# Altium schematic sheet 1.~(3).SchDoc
size 420 x 297 mm
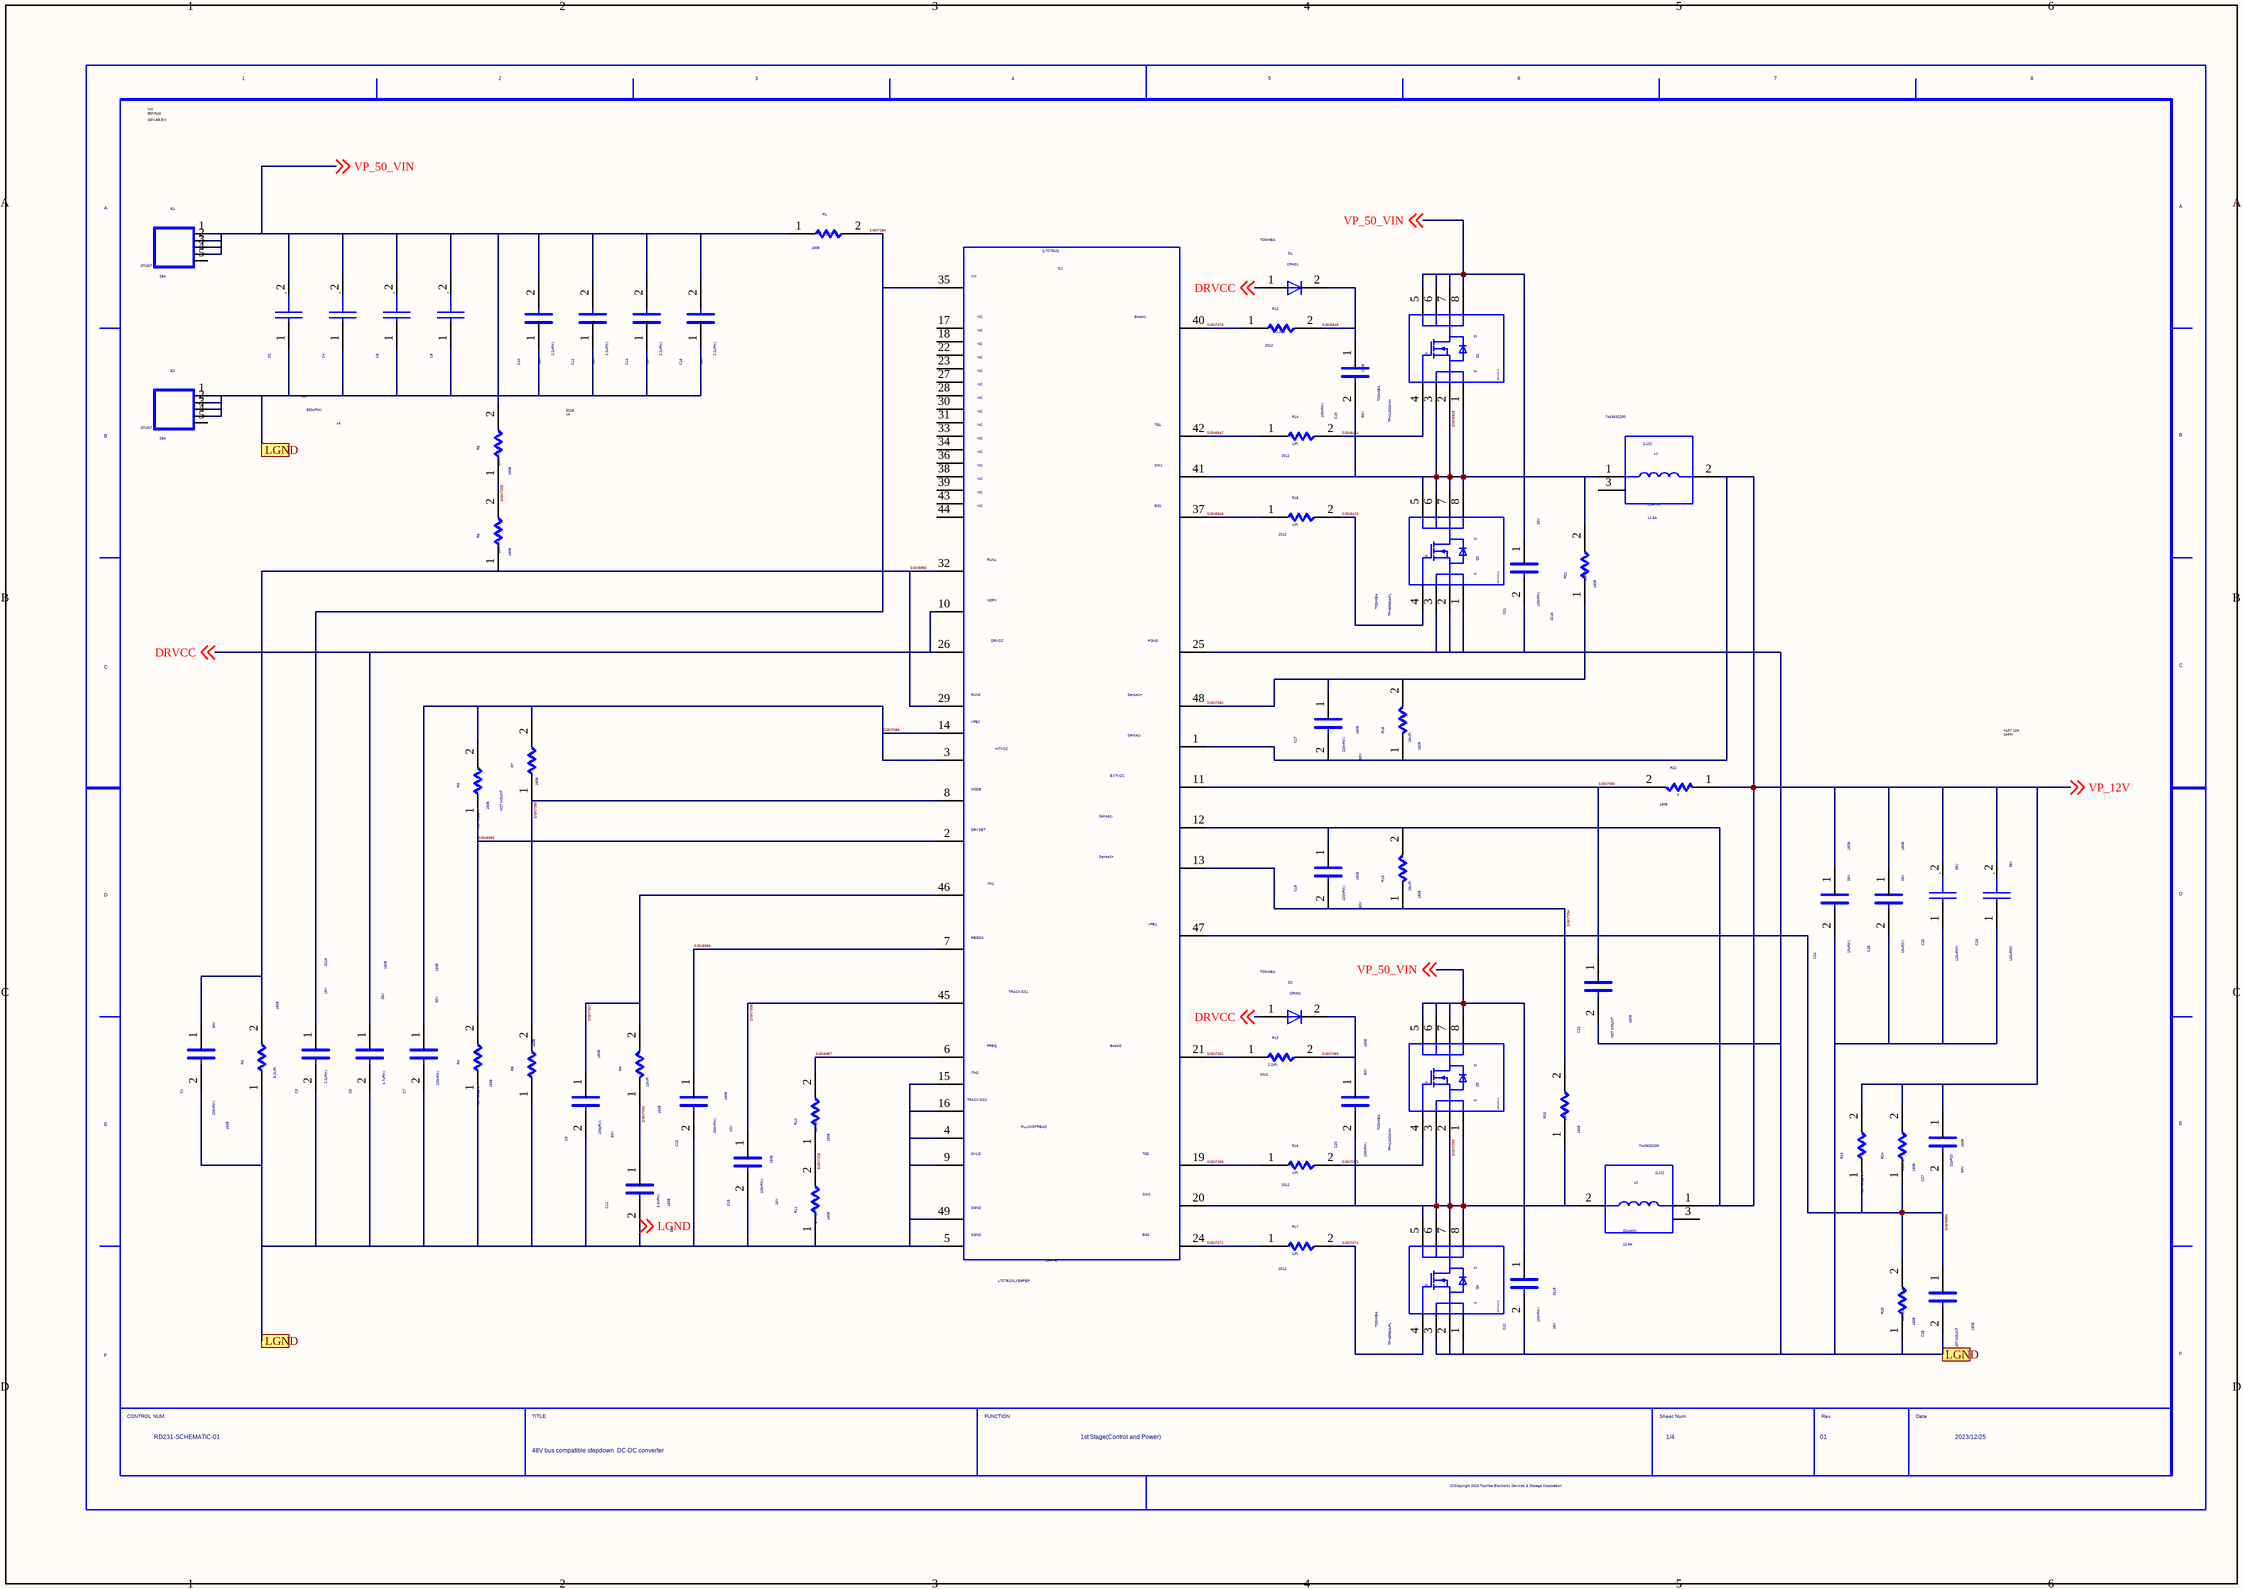
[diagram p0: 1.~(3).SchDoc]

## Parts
C1  VAL1: 100nF(K)  VAL2: 50V  SIZECODESMD: 1608  (hidden comment: C)
C2  VAL1: 560uF(M)  VAL2: 80V  (hidden comment: CP)
C3  VAL1: 2.2uF(K)  VAL2: 16V  SIZECODESMD: 3216  (hidden comment: C)
C4  CP  (value not drawn)
C5  VAL1: 4.7uF(K)  VAL2: 25V  SIZECODESMD: 1608  (hidden comment: C)
C6  CP  (value not drawn)
C7  VAL1: 100nF(K)  VAL2: 50V  SIZECODESMD: 1608  (hidden comment: C)
C8  CP  (value not drawn)
C9  VAL1: 100pF(J)  VAL2: 50V  SIZECODESMD: 1608  (hidden comment: C)
C10  VAL1: 2.2uF(K)  VAL2: 16V  (hidden comment: C)
C11  VAL1: 3.3nF(K)  VAL2: 50V  SIZECODESMD: 1608  (hidden comment: C)
C12  VAL1: 2.2uF(K)  VAL2: 16V  (hidden comment: C)
C13  VAL1: 330nF(K)  VAL2: 10V  SIZECODESMD: 1608  (hidden comment: C)
C14  VAL1: 2.2uF(K)  VAL2: 16V  (hidden comment: C)
C15  VAL1: 100nF(K)  VAL2: 16V  SIZECODESMD: 1608  (hidden comment: C)
C16  VAL1: 2.2uF(K)  VAL2: 16V  (hidden comment: C)
C17  VAL1: 220nF(K)  VAL2: 50V  SIZECODESMD: 1608  (hidden comment: C)
C18  VAL1: 220nF(K)  VAL2: 50V  SIZECODESMD: 1608  (hidden comment: C)
C19  VAL1: 100nF(K)  VAL2: 50V  SIZECODESMD: 1608  (hidden comment: C)
C20  VAL1: 100nF(K)  VAL2: 50V  SIZECODESMD: 1608  (hidden comment: C)
C21  VAL1: 100nF(K)  VAL2: 25V  SIZECODESMD: 3216  (hidden comment: C)
C22  VAL1: 100nF(K)  VAL2: 25V  SIZECODESMD: 3216  (hidden comment: C)
C23  SIZECODESMD: 1608  NOTMOUNT: NOT MOUNT  (hidden comment: C)
C24  VAL1: 10uF(K)  VAL2: 25V  SIZECODESMD: 1608  (hidden comment: C)
C25  VAL1: 10uF(K)  VAL2: 25V  SIZECODESMD: 1608  (hidden comment: C)
C26  VAL1: 120uF(M)  VAL2: 35V  (hidden comment: CP)
C27  VAL1: 22pF(D)  VAL2: 50V  SIZECODESMD: 1608  (hidden comment: C)
C28  SIZECODESMD: 1608  NOTMOUNT: NOT MOUNT  (hidden comment: C)
C29  VAL1: 120uF(M)  VAL2: 35V  (hidden comment: CP)
D1  VAL3: CRH01  USERCOMPTEXT3: TOSHIBA  (hidden comment: D)
D2  VAL3: CRH01  USERCOMPTEXT3: TOSHIBA  (hidden comment: D)
E1  VAL1: 25A  VAL3: OT-007  (hidden comment: EB)
E2  VAL1: 25A  VAL3: OT-007  (hidden comment: EB)
IC1  VAL3: LTC7810ILXE#PBF  (hidden comment: LTC7810_1)
L1  VAL1: 22uH(M)  VAL2: 12.5A  VAL3: 7443632200  (hidden comment: L1C)
L2  VAL1: 22uH(M)  VAL2: 12.5A  VAL3: 7443632200  (hidden comment: L1C)
Q1  VAL3: TPH1400ANH  USERCOMPTEXT3: TOSHIBA  (hidden comment: MFNKR2)
Q2  VAL3: TPH5R60APL  USERCOMPTEXT3: TOSHIBA  (hidden comment: MFNKR2)
Q3  VAL3: TPH1400ANH  USERCOMPTEXT3: TOSHIBA  (hidden comment: MFNKR2)
Q4  VAL3: TPH5R60APL  USERCOMPTEXT3: TOSHIBA  (hidden comment: MFNKR2)
R1  VAL1: 2.2(F)  SIZECODESMD: 1608  (hidden comment: R)
R2  VAL1: 8.2k(F)  SIZECODESMD: 1608  (hidden comment: R)
R3  NOTMOUNT: NOT MOUNT  SIZECODESMD: 1608  (hidden comment: R)
R4  NOTMOUNT: NOT MOUNT  SIZECODESMD: 1608  (hidden comment: R)
R5  VAL1: 110k(F)  SIZECODESMD: 1608  (hidden comment: R)
R6  VAL1: 110k(F)  SIZECODESMD: 1608  (hidden comment: R)
R7  SIZECODESMD: 1608  NOTMOUNT: NOT MOUNT  (hidden comment: R)
R8  VAL1: 0  SIZECODESMD: 1608  (hidden comment: R)
R9  VAL1: 12k(F)  SIZECODESMD: 1608  (hidden comment: R)
R10  VAL1: 22k(D)  SIZECODESMD: 1608  (hidden comment: R)
R11  VAL1: 2.7k(D)  SIZECODESMD: 1608  (hidden comment: R)
R12  VAL1: 2.2(F)  SIZECODESMD: 2012  (hidden comment: R)
R13  VAL1: 2.2(F)  SIZECODESMD: 2012  (hidden comment: R)
R14  VAL1: 1(F)  SIZECODESMD: 2012  (hidden comment: R)
R15  VAL1: 1(F)  SIZECODESMD: 2012  (hidden comment: R)
R16  VAL1: 1(F)  SIZECODESMD: 2012  (hidden comment: R)
R17  VAL1: 1(F)  SIZECODESMD: 2012  (hidden comment: R)
R18  VAL1: 15k(F)  SIZECODESMD: 1608  (hidden comment: R)
R19  VAL1: 15k(F)  SIZECODESMD: 1608  (hidden comment: R)
R20  VAL1: 10k(F)  SIZECODESMD: 1608  (hidden comment: R)
R21  VAL1: 10k(F)  SIZECODESMD: 1608  (hidden comment: R)
R22  VAL1: 0  SIZECODESMD: 1608  (hidden comment: R)
R23  NOTMOUNT: NOT MOUNT  (hidden comment: R)
R24  VAL1: 220k(D)  SIZECODESMD: 1608  (hidden comment: R)
R25  VAL1: 20k(D)  SIZECODESMD: 1608  (hidden comment: R)
U?  DATE: 2023/12/25  FUNCTION: 1st Stage(Control and Power)  DRAWINGNUMBER: RD231-SCHEMATIC-01  SHEETNUMBER: 1/4  REVISION: 01  TITLE: 48V bus compatible stepdown / DC-DC converter  (hidden comment: WAKU_DEF100)

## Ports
LGND

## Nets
DRVCC: C5.1 D1.1(A) D2.1(A) IC1.10 IC1.26 ; off-sheet DRVCC
LGND: C1.2 C2.1 C3.2 C4.1 C5.2 C6.1 C7.2 C8.1 C9.2 C10.1 C11.2 C12.1 C13.2 C14.1 C15.2 C16.1 C21.2 C22.2 C23.2 C24.2 C25.2 C26.1 C28.2 C29.1 E2.1 E2.2 E2.3 E2.4 IC1.4 IC1.5 IC1.9 IC1.15 IC1.16 IC1.25 IC1.49 Q2.1 Q2.2 Q2.3 Q4.1 Q4.2 Q4.3 R2.1 R4.1 R8.1 R11.1 R25.1 ; off-sheet LGND, port LGND
SIGN6423: Q2.4 R15.2
SIGN6441: Q1.4 R14.2
SIGN6926: C19.2 IC1.41 L1.1 Q1.1 Q1.2 Q1.3 Q2.5 Q2.6 Q2.7 Q2.8 R21.2
SIGN6946: IC1.37 R15.1
SIGN6947: IC1.42 R14.1
SIGN6948: C19.1 D1.2(C) R12.2
SIGN6954: C27.2 C28.1 IC1.47 R23.1 R24.1 R25.2
SIGN6957: IC1.6 R10.2
SIGN6960: C1.1 IC1.29 IC1.32 R2.2 R6.1
SIGN6989: C13.1 IC1.7
SIGN6992: IC1.2 R3.1 R4.2
SIGN7000: C11.1 R9.1
SIGN7005: C15.1 IC1.45
SIGN7007: C9.1 IC1.46 R9.2
SIGN7059: C20.2 IC1.20 L2.2 Q3.1 Q3.2 Q3.3 Q4.5 Q4.6 Q4.7 Q4.8 R20.1
SIGN7062: IC1.21 R13.1
SIGN7068: IC1.19 R16.1
SIGN7069: C20.1 D2.2(C) R13.2
SIGN7071: IC1.24 R17.1
SIGN7073: Q3.4 R16.2
SIGN7074: Q4.4 R17.2
SIGN7078: IC1.40 R12.1
SIGN7084: C3.1 IC1.35 R1.2
SIGN7088: C7.1 IC1.3 IC1.14 R3.2 R7.2
SIGN7089: IC1.8 R7.1 R8.2
SIGN7090: C23.1 IC1.11 R22.2
SIGN7092: C17.1 IC1.48 R18.2 R21.1
SIGN7094: C18.2 IC1.13 R19.1 R20.2
SIGN7205: R5.1 R6.2
SIGN7208: R10.1 R11.2
VP_12V: C17.2 C18.1 C24.1 C25.1 C26.2 C27.1 C29.2 IC1.1 IC1.12 L1.2 L2.1 R18.1 R19.2 R22.1 R23.2 R24.2 ; off-sheet VP_12V
VP_50_VIN: C2.2 C4.2 C6.2 C8.2 C10.2 C12.2 C14.2 C16.2 C21.1 C22.1 E1.1 E1.2 E1.3 E1.4 Q1.5 Q1.6 Q1.7 Q1.8 Q3.5 Q3.6 Q3.7 Q3.8 R1.1 R5.2 ; off-sheet VP_50_VIN

Not connected (* = marked no-connect by the designer): E1 5; E2 5; IC1 17 18 22 23 27 28 30 31 33 34 36 38 39 43 44; L1 3; L2 3

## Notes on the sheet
- (40V-59.5V)
- Vin
  (50Vtyp)
- x4
- 3216
  x4
- +12V 12A
  144W
- (near IC1) 100kHz

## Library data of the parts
C1 C7 C19 C20 C23 = C: PARTCOMMENT: 代表セル<KC0008> がフットプリントに登録されていません。; FNPARTSNAMEG: CHIP CERAMIC CAPACITOR (1608); OriginalSymbolOrigin: (2540,7620); FNCLASSCODEG: P03-03; PCODE: P03B000001KW; USEWITHSCHEMA: YES; MFMOUNTSYMBOLP: 80; FUNCN: GDM030001005; MFFORMINGDIVP: KC; MFPACKAGEMETHOP: S; MFSOLDERINGPROP: .; COMPONENTNAME: GDM030001005_package; GCOUNT: 1
C2 C26 C29 = CP: FNPARTSCODEG: C; FNPARTSNAMEG: CHIP ALUMINUM ELECTROLYTIC CAPACITOR; SAVEAREA0: -1450,-153,20294,13055; SAVECOUNT: 52; TIME: 15:02:55; UPDATEUSER: fukuda-y; UPDATETIME: 16:13:42; OriginalSymbolOrigin: (2540,10160); USEWITHSCHEMA: YES; FUNCN: G36030155199; GCOUNT: 1; COMPONENTNAME: G36030155199_package; FNCLASSCODEG: P03-01; PCODE: P03090017118; MFMOUNTSYMBOLP: 80; MFFORMINGDIVP: KD; MFPACKAGEMETHOP: S; MFSOLDERINGPROP: F
C3 = C: FNPARTSNAMEG: CHIP CERAMIC CAPACITOR (3216); OriginalSymbolOrigin: (2540,7620); FNCLASSCODEG: P03-03; PCODE: P03042997321; USEWITHSCHEMA: YES; MFMOUNTSYMBOLP: 90; FUNCN: G36030110013; MFFORMINGDIVP: KC; MFPACKAGEMETHOP: S; MFSOLDERINGPROP: .; COMPONENTNAME: G36030110013_package; GCOUNT: 1; TOLERANCE: K
C4 C6 C8 = CP: FNPARTSCODEG: C; FNPARTSNAMEG: CHIP ALUMINUM ELECTROLYTIC CAPACITOR; SAVEAREA0: -1450,-153,20294,13055; SAVECOUNT: 52; TIME: 15:02:55; UPDATEUSER: fukuda-y; UPDATETIME: 16:13:42; OriginalSymbolOrigin: (2540,10160); USEWITHSCHEMA: YES; FUNCN: G36030155199; GCOUNT: 1; COMPONENTNAME: G36030155199_package; VAL1: 560uF(M); VAL2: 80V; FNCLASSCODEG: P03-01; PCODE: P03090017118; MFMOUNTSYMBOLP: 80; MFFORMINGDIVP: KD; MFPACKAGEMETHOP: S; MFSOLDERINGPROP: F
C5 = C: PARTCOMMENT: 代表セル<KC0008> がフットプリントに登録されていません。; FNPARTSNAMEG: CHIP CERAMIC CAPACITOR (1608); OriginalSymbolOrigin: (2540,7620); FNCLASSCODEG: P03-03; PCODE: P03B000001NY; USEWITHSCHEMA: YES; MFMOUNTSYMBOLP: 80; FUNCN: GDM030001182; MFFORMINGDIVP: KC; MFPACKAGEMETHOP: S; MFSOLDERINGPROP: .; COMPONENTNAME: GDM030001182_package; GCOUNT: 1
C9 = C: FNPARTSNAMEG: CHIP CERAMIC CAPACITOR (1608); OriginalSymbolOrigin: (2540,7620); FNCLASSCODEG: P03-03; PCODE: P03039307126; USEWITHSCHEMA: YES; MFMOUNTSYMBOLP: 80; FUNCN: G36030011181; MFFORMINGDIVP: KC; MFPACKAGEMETHOP: S; MFSOLDERINGPROP: .; COMPONENTNAME: G36030011181_package; GCOUNT: 1; TOLERANCE: J
C10 C12 C14 C16 = C: FNPARTSNAMEG: CHIP CERAMIC CAPACITOR (3216); OriginalSymbolOrigin: (2540,7620); FNCLASSCODEG: P03-03; USEWITHSCHEMA: YES; FUNCN: G36030110013; SIZECODESMD: 3216; COMPONENTNAME: G36030110013_package; GCOUNT: 1; PCODE: P03042997321; MFMOUNTSYMBOLP: 90; MFFORMINGDIVP: KC; MFPACKAGEMETHOP: S; MFSOLDERINGPROP: .; TOLERANCE: K
C11 = C: FNPARTSNAMEG: CHIP CERAMIC CAPACITOR (1608); OriginalSymbolOrigin: (2540,7620); FNCLASSCODEG: P03-03; PCODE: P03039A11122; USEWITHSCHEMA: YES; MFMOUNTSYMBOLP: 80; FUNCN: G36030011075; MFFORMINGDIVP: KC; MFPACKAGEMETHOP: S; MFSOLDERINGPROP: .; COMPONENTNAME: G36030011075_package; GCOUNT: 1; TOLERANCE: K
C13 = C: FNPARTSNAMEG: CHIP CERAMIC CAPACITOR (1608); OriginalSymbolOrigin: (2540,7620); FNCLASSCODEG: P03-03; PCODE: P03039ABF120; USEWITHSCHEMA: YES; MFMOUNTSYMBOLP: 80; FUNCN: G36030104111; MFFORMINGDIVP: KC; MFPACKAGEMETHOP: S; MFSOLDERINGPROP: .; COMPONENTNAME: G36030104111_package; GCOUNT: 1
C15 = C: FNPARTSNAMEG: CHIP CERAMIC CAPACITOR (1608); OriginalSymbolOrigin: (2540,7620); FNCLASSCODEG: P03-03; PCODE: P03039996139; USEWITHSCHEMA: YES; MFMOUNTSYMBOLP: 80; FUNCN: G36030011419; MFFORMINGDIVP: KC; MFPACKAGEMETHOP: S; MFSOLDERINGPROP: .; COMPONENTNAME: G36030011419_package; GCOUNT: 1
C17 C18 = C: FNPARTSNAMEG: CHIP CERAMIC CAPACITOR (1608); OriginalSymbolOrigin: (2540,7620); FNCLASSCODEG: P03-03; PCODE: P03039ABG127; USEWITHSCHEMA: YES; MFMOUNTSYMBOLP: 80; FUNCN: G36030104128; MFFORMINGDIVP: KC; MFPACKAGEMETHOP: S; MFSOLDERINGPROP: .; COMPONENTNAME: G36030104128_package; GCOUNT: 1
C21 C22 = C: FNPARTSNAMEG: CHIP CERAMIC CAPACITOR (3216); OriginalSymbolOrigin: (2540,7620); FNCLASSCODEG: P03-03; PCODE: P03042006320; USEWITHSCHEMA: YES; MFMOUNTSYMBOLP: 90; FUNCN: G36030031080; MFFORMINGDIVP: KC; MFPACKAGEMETHOP: S; MFSOLDERINGPROP: .; COMPONENTNAME: G36030031080_package; GCOUNT: 1; TOLERANCE: K
C24 C25 = C: FNPARTSNAMEG: CHIP CERAMIC CAPACITOR (1608); OriginalSymbolOrigin: (2540,7620); FNCLASSCODEG: P03-03; PCODE: P03B000000MS; USEWITHSCHEMA: YES; MFMOUNTSYMBOLP: 80; FUNCN: GDM030000053; MFFORMINGDIVP: KC; MFPACKAGEMETHOP: S; MFSOLDERINGPROP: .; COMPONENTNAME: GDM030000053_package; GCOUNT: 1
C27 C28 = C: FNPARTSNAMEG: CHIP CERAMIC CAPACITOR (1608); OriginalSymbolOrigin: (2540,7620); FNCLASSCODEG: P03-03; PCODE: P03039185229; USEWITHSCHEMA: YES; MFMOUNTSYMBOLP: 80; FUNCN: G36030011013; MFFORMINGDIVP: KC; MFPACKAGEMETHOP: S; MFSOLDERINGPROP: .; COMPONENTNAME: G36030011013_package; GCOUNT: 1; TOLERANCE: D
D1 D2 = D: SAVEAREA0: -565,-171,12979,8058; SAVECOUNT: 3; TIME: 14:49:55; UPDATEUSER: 19870035; UPDATETIME: 14:20:16; OriginalSymbolOrigin: (5080,5080); USEWITHSCHEMA: YES; VAL1: 1A; OUMEMAKERKATAMEI: CMF02(TE12R,Q); COMP: 5P9L1110P002; OUMEMAKER: 東芝; VAL2: 200V
E1 E2 = EB: SAVEAREA0: -10166,-6669,19798,9727; TIME: 17:33:04; UPDATEUSER: sptcae13; SAVECOUNT: 1; OriginalSymbolOrigin: (0,8890); COMP: 5P9L1232P001
IC1 = LTC7810_1: TIME: 17:42:33; UPDATEUSER: q91873sr; UPDATETIME: 00:58:17; SAVECOUNT: 171; SAVEAREA0: -56936,59772,124648,157086; OriginalSymbolOrigin: (5080,193040); USEWITHSCHEMA: YES; COMPONENTNAME: LTC7810_1.LTC7810_1; GCOUNT: 1
L1 L2 = L1C: SAVECOUNT: 6; SAVEAREA0: -5636,-341,27978,18652; OriginalSymbolOrigin: (5080,15240); USEWITHSCHEMA: YES; OUMEMAKERKATAMEI: 7443630140; GCOUNT: 1; OUMEMAKER: WURTH; COMPONENTNAME: L1C_L1C
Q1-Q4 = MFNKR2: SAVEAREA0: -9199,-39,32138,22820; TIME: 18:57:44; UPDATEUSER: q91866sr; UPDATETIME: 12:36:02; SAVECOUNT: 10; OriginalSymbolOrigin: (5080,20320); USEWITHSCHEMA: YES; OUMEMAKERKATAMEI: TPH6R003NL; COMPONENTNAME: MFNKR2_MFNKR2; GCOUNT: 1
R1 = R: FNPARTSNAMEG: CHIP RESISTOR (1608); OriginalSymbolOrigin: (5080,5080); FNCLASSCODEG: P01-08; PCODE: P01183001112; USEWITHSCHEMA: YES; VAL2: 100mW; NUMBEROFELEMENT: 0; COMP: G36010141013; MFFORMINGDIVP: KC; MFPACKAGEMETHOP: S; MFSOLDERINGPROP: .; MFMOUNTSYMBOLP: 80; COMPONENTNAME: G36010141013_package
R2 = R: FNPARTSNAMEG: CHIP RESISTOR (1608); OriginalSymbolOrigin: (5080,5080); FNCLASSCODEG: P01-08; PCODE: P01042507328; USEWITHSCHEMA: YES; VAL2: 100mW; NUMBEROFELEMENT: 0; COMP: G36010027188; MFFORMINGDIVP: KC; MFPACKAGEMETHOP: S; MFSOLDERINGPROP: .; MFMOUNTSYMBOLP: 80; COMPONENTNAME: G36010027188_package; GCOUNT: 1; TOLERANCE: F
R3 R4 = R: FNPARTSNAMEG: CHIP RESISTOR (1608); OriginalSymbolOrigin: (5080,5080); FNCLASSCODEG: P01-08; PCODE: P01042049A26; USEWITHSCHEMA: YES; NUMBEROFELEMENT: 0; COMP: G36010027034; MFFORMINGDIVP: KC; MFPACKAGEMETHOP: S; MFSOLDERINGPROP: .; MFMOUNTSYMBOLP: 80; COMPONENTNAME: G36010027034_package; GCOUNT: 1; TOLERANCE: F
R5 R6 = R: FNPARTSNAMEG: CHIP RESISTOR (1608); OriginalSymbolOrigin: (5080,5080); FNCLASSCODEG: P01-08; PCODE: P01042519628; USEWITHSCHEMA: YES; VAL2: 100mW; NUMBEROFELEMENT: 0; COMP: G36010027300; MFFORMINGDIVP: KC; MFPACKAGEMETHOP: S; MFSOLDERINGPROP: .; MFMOUNTSYMBOLP: 80; COMPONENTNAME: G36010027300_package; GCOUNT: 1; TOLERANCE: F
R7 = R: FNPARTSNAMEG: CHIP RESISTOR (1608); OriginalSymbolOrigin: (5080,5080); FNCLASSCODEG: P01-08; PCODE: P01042045226; USEWITHSCHEMA: YES; NUMBEROFELEMENT: 0; COMP: G36010027133; MFFORMINGDIVP: KC; MFPACKAGEMETHOP: S; MFSOLDERINGPROP: .; MFMOUNTSYMBOLP: 80; COMPONENTNAME: G36010027133_package; GCOUNT: 1; TOLERANCE: F
R8 = R: FNPARTSNAMEG: CHIP RESISTOR (1608); OriginalSymbolOrigin: (5080,5080); FNCLASSCODEG: P01-08; PCODE: P01042207426; USEWITHSCHEMA: YES; COMP: G36010027089; MFFORMINGDIVP: KC; MFPACKAGEMETHOP: S; MFSOLDERINGPROP: .; MFMOUNTSYMBOLP: 80; COMPONENTNAME: G36010027089_package; GCOUNT: 1; TOLERANCE: F
R9 = R: FNPARTSNAMEG: CHIP RESISTOR (1608); OriginalSymbolOrigin: (5080,5080); FNCLASSCODEG: P01-08; USEWITHSCHEMA: YES; VAL2: 100mW; COMP: G36010027041; PCODE: P01042097423; NUMBEROFELEMENT: 0; MFMOUNTSYMBOLP: 80; MFFORMINGDIVP: KC; MFPACKAGEMETHOP: S; MFSOLDERINGPROP: .; TOLERANCE: F; COMPONENTNAME: G36010027041_package; GCOUNT: 1
R10 = R: FNPARTSNAMEG: CHIP RESISTOR (1608); OriginalSymbolOrigin: (5080,5080); FNCLASSCODEG: P01-08; USEWITHSCHEMA: YES; VAL2: 62.5mW; COMP: G36010129578; PCODE: P01119059118; NUMBEROFELEMENT: 0; MFMOUNTSYMBOLP: 80; MFFORMINGDIVP: KC; MFPACKAGEMETHOP: S; MFSOLDERINGPROP: .; COMPONENTNAME: G36010129578_package; GCOUNT: 1
R11 = R: FNPARTSNAMEG: CHIP RESISTOR (1608); OriginalSymbolOrigin: (5080,5080); FNCLASSCODEG: P01-08; USEWITHSCHEMA: YES; VAL2: 62.5mW; COMP: G36010129356; PCODE: P01117039112; NUMBEROFELEMENT: 0; MFMOUNTSYMBOLP: 80; MFFORMINGDIVP: KC; MFPACKAGEMETHOP: S; MFSOLDERINGPROP: .; COMPONENTNAME: G36010129356_package; GCOUNT: 1
R12 R13 = R: FNPARTSNAMEG: CHIP RESISTOR (2012); OriginalSymbolOrigin: (5080,5080); FNCLASSCODEG: P01-08; PCODE: P01048019214; USEWITHSCHEMA: YES; VAL2: 125mW; NUMBEROFELEMENT: 0; MFMOUNTSYMBOLP: 90; FUNCN: G36010106012; MFFORMINGDIVP: KC; MFPACKAGEMETHOP: S; MFSOLDERINGPROP: .; COMPONENTNAME: G36010106012_package; GCOUNT: 1
R14-R17 = R: FNPARTSNAMEG: CHIP RESISTOR (2012); OriginalSymbolOrigin: (5080,5080); FNCLASSCODEG: P01-08; PCODE: P01048017210; USEWITHSCHEMA: YES; VAL2: 125mW; NUMBEROFELEMENT: 0; MFMOUNTSYMBOLP: 90; FUNCN: G36010106081; MFFORMINGDIVP: KC; MFPACKAGEMETHOP: S; MFSOLDERINGPROP: .; COMPONENTNAME: G36010106081_package; GCOUNT: 1
R18 R19 = R: FNPARTSNAMEG: CHIP RESISTOR (1608); OriginalSymbolOrigin: (5080,5080); FNCLASSCODEG: P01-08; USEWITHSCHEMA: YES; VAL2: 100mW; COMP: G36010027058; PCODE: P01042113727; NUMBEROFELEMENT: 0; MFMOUNTSYMBOLP: 80; MFFORMINGDIVP: KC; MFPACKAGEMETHOP: S; MFSOLDERINGPROP: .; TOLERANCE: F; COMPONENTNAME: G36010027058_package; GCOUNT: 1
R20 R21 = R: FNPARTSNAMEG: CHIP RESISTOR (1608); OriginalSymbolOrigin: (5080,5080); FNCLASSCODEG: P01-08; USEWITHSCHEMA: YES; VAL2: 100mW; COMP: G5101105R107; PCODE: P01042424625; NUMBEROFELEMENT: 0; MFMOUNTSYMBOLP: 80; MFFORMINGDIVP: KC; MFPACKAGEMETHOP: S; MFSOLDERINGPROP: .; COMPONENTNAME: G5101105R107_package; GCOUNT: 1
R22 = R: PARTCOMMENT: 代表セル<KC0008> がフットプリントに登録されていません。; FNPARTSNAMEG: CHIP JUMPER 1608TYPE; OriginalSymbolOrigin: (5080,5080); FNCLASSCODEG: P01-08; USEWITHSCHEMA: YES; FUNCN: K0100346; COMPONENTNAME: K0100346_package; GCOUNT: 1
R23 = R: FNPARTSNAMEG: CHIP RESISTOR (1608); OriginalSymbolOrigin: (5080,5080); FNCLASSCODEG: P01-08; USEWITHSCHEMA: YES; COMP: G5101106F106; PCODE: P01042680229; NUMBEROFELEMENT: 0; MFMOUNTSYMBOLP: 80; MFFORMINGDIVP: KC; MFPACKAGEMETHOP: S; MFSOLDERINGPROP: .; COMPONENTNAME: G5101106F106_package; GCOUNT: 1; SIZECODESMD: 1608
R24 = R: FNPARTSNAMEG: CHIP RESISTOR (1608); OriginalSymbolOrigin: (5080,5080); FNCLASSCODEG: P01-08; USEWITHSCHEMA: YES; VAL2: 62.5mW; COMP: G5101109J104; PCODE: P01042669620; NUMBEROFELEMENT: 0; MFMOUNTSYMBOLP: 80; MFFORMINGDIVP: KC; MFPACKAGEMETHOP: S; MFSOLDERINGPROP: .; COMPONENTNAME: G5101109J104_package; GCOUNT: 1
R25 = R: FNPARTSNAMEG: CHIP RESISTOR (1608); OriginalSymbolOrigin: (5080,5080); FNCLASSCODEG: P01-08; USEWITHSCHEMA: YES; VAL2: 62.5mW; COMP: G36010129493; PCODE: P01117053118; NUMBEROFELEMENT: 0; MFMOUNTSYMBOLP: 80; MFFORMINGDIVP: KC; MFPACKAGEMETHOP: S; MFSOLDERINGPROP: .; COMPONENTNAME: G36010129493_package; GCOUNT: 1
U? = WAKU_DEF100: PLOTTIME: HH:MM; SAVEAREA0: -56280,0,471144,298016; TIME: 20:22:11; UPDATEUSER: sptcae13; UPDATETIME: 11:34:32; SAVECOUNT: 8; OriginalSymbolOrigin: (10160,284480)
